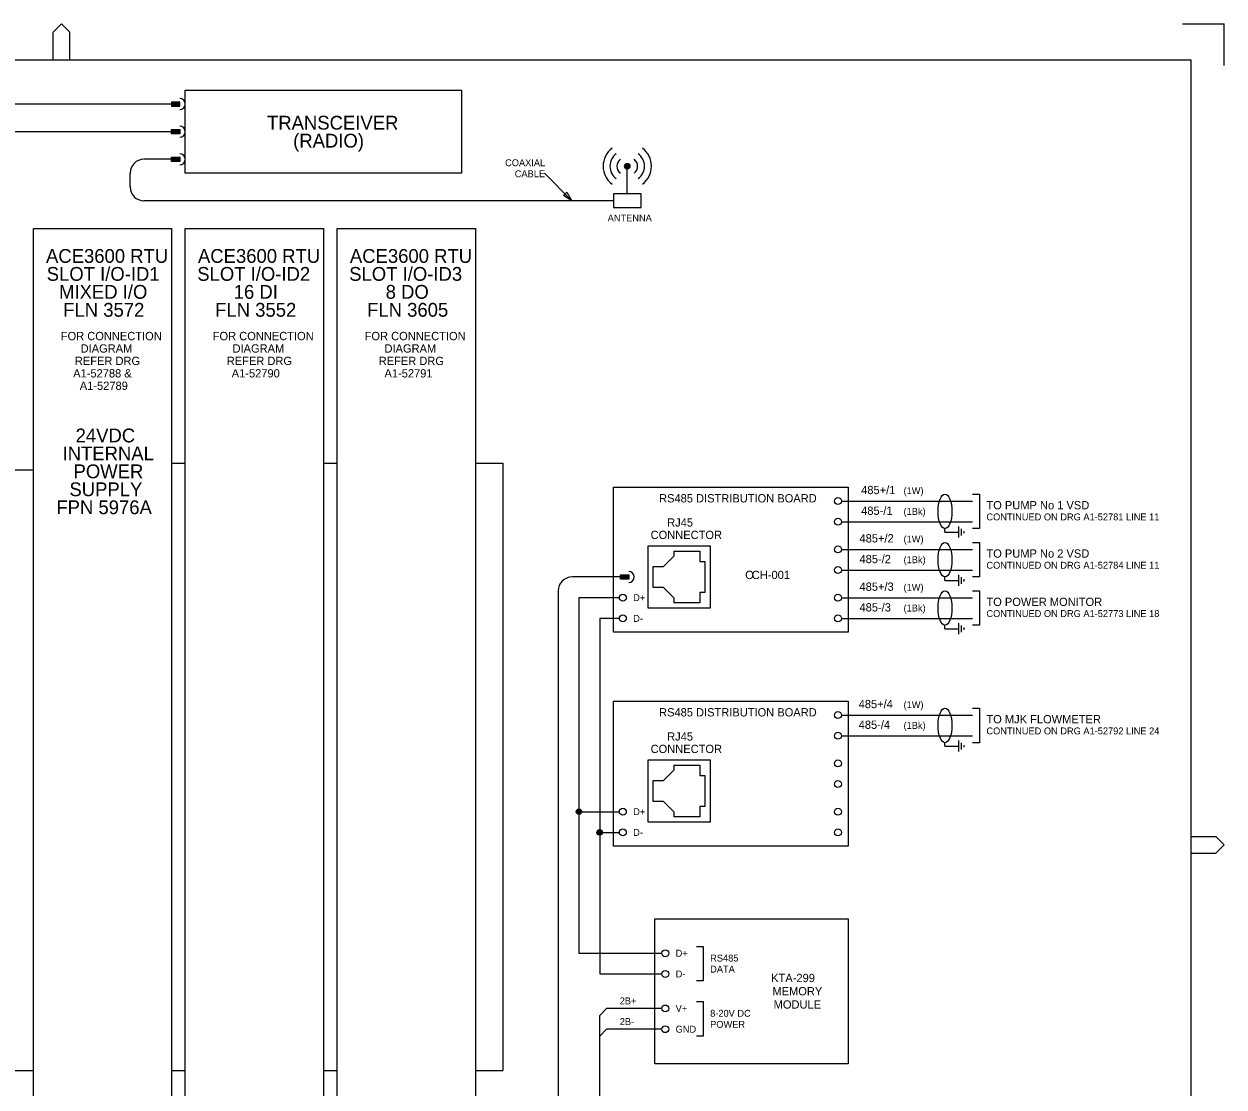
# Model space of a CAD drawing. Extents: x 0 to 841, y 0 to 594.
# Drawn here: x 406.6 to 841, y 209.1 to 594 of the extents above; entities that cross this region are included whole.
import ezdxf

# ---------------------------------------------------------------- set-up
doc = ezdxf.new("R2010")
doc.units = 0
for name, color, linetype in [('A1BORDER', 7, 'Continuous'), ('Level 1', 7, 'Continuous'), ('Level 10', 7, 'Continuous')]:
    doc.layers.add(name, color=color, linetype=linetype)

msp = doc.modelspace()

# ---------------------------------------------------------------- linework, layer by layer
at = {"layer": 'A1BORDER'}
for p, q in [((417.19, 591), (420.19, 594)), ((417.19, 581), (417.19, 591)), ((423.19, 591), (420.19, 594)), ((423.19, 581), (423.19, 591)), ((826, 594), (841, 594)), ((841, 579), (841, 594)), ((28, 581), (829, 581)), ((829, 581), (829, 15)), ((829, 299.76), (838, 299.76)), ((838, 299.76), (841, 296.76)), ((838, 293.76), (841, 296.76)), ((829, 293.76), (838, 293.76))]:
    msp.add_line(p, q, dxfattribs=at)
at = {"layer": 'Level 1'}
for p, q in [((460, 565), (395, 565)), ((463, 565.5), (460, 565.5)), ((463, 565.25), (460, 565.25)), ((463, 565), (460, 565)), ((463, 564.75), (460, 564.75)), ((463, 564.5), (460, 564.5)), ((460, 555), (235, 555)), ((460, 545), (450, 545)), ((445, 535), (445, 540)), ((604.97, 530), (594.97, 540)), ((624.97, 532.5), (624.97, 542.5)), ((620, 530), (450, 530)), ((460, 435), (465, 435)), ((515, 435), (520, 435)), ((570, 435), (580, 435)), ((580, 435), (580, 215)), ((370, 432.5), (410, 432.5)), ((702.5, 421.25), (750, 421.25)), ((702.5, 413.75), (750, 413.75)), ((740, 410), (740, 411.25)), ((740, 410), (745, 410)), ((638.12, 397.5), (641.88, 401.25)), ((641.88, 403.12), (651.25, 403.12)), ((641.88, 403.12), (641.88, 401.25)), ((651.25, 403.12), (651.25, 399.38)), ((702.5, 403.75), (750, 403.75)), ((634.38, 390), (634.38, 397.5)), ((634.38, 397.5), (638.12, 397.5)), ((651.25, 399.38), (653.12, 399.38)), ((653.12, 399.38), (653.12, 388.12)), ((702.5, 396.25), (750, 396.25)), ((622.5, 393.75), (605, 393.75)), ((740, 392.5), (740, 393.75)), ((740, 392.5), (745, 392.5)), ((600, 388.75), (600, 175)), ((638.12, 390), (634.38, 390)), ((641.88, 386.25), (638.12, 390)), ((653.12, 388.12), (651.25, 388.12)), ((651.25, 388.12), (651.25, 384.38)), ((622.13, 386.25), (607.5, 386.25)), ((607.5, 386.25), (607.5, 257.5)), ((641.88, 386.25), (641.88, 384.38)), ((651.25, 384.38), (641.88, 384.38)), ((702.5, 386.25), (750, 386.25)), ((622.13, 378.75), (615, 378.75)), ((615, 378.75), (615, 250)), ((702.5, 378.75), (750, 378.75)), ((740, 375), (740, 376.25)), ((740, 375), (745, 375)), ((702.5, 343.75), (750, 343.75)), ((702.5, 336.25), (750, 336.25)), ((740, 332.5), (740, 333.75)), ((740, 332.5), (745, 332.5)), ((638.12, 320), (641.88, 323.75)), ((641.88, 325.62), (651.25, 325.62)), ((641.88, 325.62), (641.88, 323.75)), ((651.25, 325.62), (651.25, 321.88)), ((651.25, 321.88), (653.12, 321.88)), ((653.12, 321.88), (653.12, 310.62)), ((634.38, 312.5), (634.38, 320)), ((634.38, 320), (638.12, 320)), ((607.5, 308.75), (622.13, 308.75)), ((638.12, 312.5), (634.38, 312.5)), ((641.88, 308.75), (638.12, 312.5)), ((641.88, 308.75), (641.88, 306.88)), ((653.12, 310.62), (651.25, 310.62)), ((651.25, 310.62), (651.25, 306.88)), ((651.25, 306.88), (641.88, 306.88)), ((615, 301.25), (622.13, 301.25)), ((607.5, 257.5), (637.5, 257.5)), ((615, 250), (637.5, 250)), ((617.5, 237.5), (615, 235)), ((615, 145), (615, 235)), ((637.5, 237.5), (617.5, 237.5)), ((617.5, 230), (615, 227.5)), ((637.5, 230), (617.5, 230)), ((370, 215), (410, 215)), ((460, 215), (465, 215)), ((515, 215), (520, 215)), ((570, 215), (580, 215))]:
    msp.add_line(p, q, dxfattribs=at)
for points in [[(465, 570), (565, 570), (565, 540), (465, 540)], [(603.11, 533.09), (604.97, 530), (601.88, 531.86)], [(619.97, 527.5), (629.97, 527.5), (629.97, 532.5), (619.97, 532.5)], [(410, 520), (460, 520), (460, 180), (410, 180)], [(465, 520), (515, 520), (515, 180), (465, 180)], [(520, 520), (570, 520), (570, 180), (520, 180)], [(620, 426.25), (705, 426.25), (705, 373.75), (620, 373.75)], [(655, 382.5), (632.5, 382.5), (632.5, 405), (655, 405)], [(620, 348.75), (705, 348.75), (705, 296.25), (620, 296.25)], [(655, 305), (632.5, 305), (632.5, 327.5), (655, 327.5)], [(635, 270), (705, 270), (705, 217.5), (635, 217.5)]]:
    msp.add_lwpolyline(points, close=True, dxfattribs=at)
for points in [[(750, 423.75), (752.5, 423.75), (752.5, 411.25), (750, 411.25)], [(750, 406.25), (752.5, 406.25), (752.5, 393.75), (750, 393.75)], [(750, 388.75), (752.5, 388.75), (752.5, 376.25), (750, 376.25)], [(750, 346.25), (752.5, 346.25), (752.5, 333.75), (750, 333.75)], [(650, 260), (652.5, 260), (652.5, 247.5), (650, 247.5)], [(650, 240), (652.5, 240), (652.5, 227.5), (650, 227.5)]]:
    msp.add_lwpolyline(points, dxfattribs=at)
for centre, radius, start, end in [((624.35, 542.5), 8.12, 126.8699, 233.1301), ((625.6, 542.5), 8.12, 306.8699, 53.1301), ((450, 540), 5, 90, 180), ((624.35, 542.5), 5.62, 126.8699, 233.1301), ((624.35, 542.5), 3.12, 126.8699, 233.1301), ((625.6, 542.5), 3.12, 306.8699, 53.1301), ((625.6, 542.5), 5.62, 306.8699, 53.1301), ((450, 535), 5, 180, 270), ((605, 388.75), 5, 90, 180)]:
    msp.add_arc(centre, radius, start, end, dxfattribs=at)
for centre in [(740, 417.5), (740, 400), (740, 382.5), (740, 340)]:
    msp.add_ellipse(centre, major_axis=(0, 6.25), ratio=0.4, dxfattribs=at)
at = {"layer": 'Level 10'}
for p, q in [((463, 555.48), (460, 555.48)), ((463, 555.18), (460, 555.18)), ((463, 554.88), (460, 554.88)), ((463, 554.58), (460, 554.58)), ((463, 554.28), (460, 554.28)), ((463, 545.48), (460, 545.48)), ((463, 545.18), (460, 545.18)), ((463, 544.88), (460, 544.88)), ((463, 544.58), (460, 544.58)), ((463, 544.28), (460, 544.28)), ((624.26, 543.2), (625.68, 543.2)), ((624.97, 543.5), (624.97, 543.5)), ((623.98, 542.6), (625.96, 542.6)), ((623.99, 542.3), (625.95, 542.3)), ((624.05, 542.9), (625.89, 542.9)), ((624.1, 542), (625.84, 542)), ((624.37, 541.7), (625.57, 541.7)), ((745, 408), (745, 412)), ((746, 408.8), (746, 411.2)), ((747, 409.6), (747, 410.4)), ((625.5, 394.23), (622.5, 394.23)), ((625.5, 393.93), (622.5, 393.93)), ((625.5, 393.63), (622.5, 393.63)), ((625.5, 393.33), (622.5, 393.33)), ((625.5, 393.03), (622.5, 393.03)), ((745, 390.5), (745, 394.5)), ((746, 391.3), (746, 393.7)), ((747, 392.1), (747, 392.9)), ((745, 373), (745, 377)), ((746, 373.8), (746, 376.2)), ((747, 374.6), (747, 375.4)), ((745, 330.5), (745, 334.5)), ((746, 331.3), (746, 333.7)), ((747, 332.1), (747, 332.9)), ((606.5, 308.75), (606.5, 308.75)), ((606.8, 308.04), (606.8, 309.46)), ((607.1, 307.83), (607.1, 309.67)), ((607.4, 307.76), (607.4, 309.74)), ((607.7, 307.77), (607.7, 309.73)), ((608, 307.88), (608, 309.62)), ((608.3, 308.15), (608.3, 309.35)), ((614, 301.25), (614, 301.25)), ((614.3, 300.54), (614.3, 301.96)), ((614.6, 300.33), (614.6, 302.17)), ((614.9, 300.26), (614.9, 302.24)), ((615.2, 300.27), (615.2, 302.23)), ((615.5, 300.38), (615.5, 302.12)), ((615.8, 300.65), (615.8, 301.85))]:
    msp.add_line(p, q, dxfattribs=at)
for points in [[(463, 565.75), (460, 565.75), (460, 564.25), (463, 564.25)], [(463, 554.25), (460, 554.25), (460, 555.75), (463, 555.75)], [(463, 544.25), (460, 544.25), (460, 545.75), (463, 545.75)], [(625.5, 393), (622.5, 393), (622.5, 394.5), (625.5, 394.5)]]:
    msp.add_lwpolyline(points, close=True, dxfattribs=at)
for centre, radius in [((624.97, 542.5), 1), ((701.25, 421.25), 1.25), ((701.25, 413.75), 1.25), ((701.25, 403.75), 1.25), ((701.25, 396.25), 1.25), ((623.38, 386.25), 1.25), ((701.25, 386.25), 1.25), ((623.38, 378.75), 1.25), ((701.25, 378.75), 1.25), ((701.25, 343.75), 1.25), ((701.25, 336.25), 1.25), ((701.25, 326.25), 1.25), ((701.25, 318.75), 1.25), ((607.5, 308.75), 1), ((623.38, 308.75), 1.25), ((701.25, 308.75), 1.25), ((615, 301.25), 1), ((623.38, 301.25), 1.25), ((701.25, 301.25), 1.25), ((638.75, 257.5), 1.25), ((638.75, 250), 1.25), ((638.75, 237.5), 1.25), ((638.75, 230), 1.25)]:
    msp.add_circle(centre, radius, dxfattribs=at)
for centre in [(463, 565), (463, 555), (463, 545), (625.5, 393.75)]:
    msp.add_arc(centre, 2, 270, 90, dxfattribs=at)

# ---------------------------------------------------------------- texts
at = {"layer": 'Level 1'}
for s, height, p in [('TRANSCEIVER', 5, (494.58, 555.75)), ('(RADIO)', 5, (504.04, 549.25)), ('COAXIAL', 2.5, (580.77, 542.5)), ('CABLE', 2.5, (584.26, 538.5)), ('ANTENNA', 2.5, (617.9, 522.5)), ('ACE3600 RTU', 5, (414.58, 507.5)), ('ACE3600 RTU', 5, (469.58, 507.5)), ('ACE3600 RTU', 5, (524.58, 507.5)), ('SLOT I/O-ID1', 5, (414.83, 501)), ('SLOT I/O-ID2', 5, (469.33, 501)), ('SLOT I/O-ID3', 5, (524.33, 501)), ('MIXED I/O', 5, (419.31, 494.5)), ('16 DI', 5, (482.53, 494.5)), ('8 DO', 5, (537.53, 494.5)), ('FLN 3572', 5, (420.81, 488)), ('FLN 3552', 5, (475.81, 488)), ('FLN 3605', 5, (530.81, 488)), ('FOR CONNECTION', 3, (419.93, 479.5)), ('FOR CONNECTION', 3, (474.93, 479.5)), ('FOR CONNECTION', 3, (529.93, 479.5)), ('DIAGRAM', 3, (427.1, 475)), ('DIAGRAM', 3, (482.1, 475)), ('DIAGRAM', 3, (537.1, 475)), ('REFER DRG', 3, (425.01, 470.5)), ('REFER DRG', 3, (480.01, 470.5)), ('REFER DRG', 3, (535.01, 470.5)), ('A1-52788 &', 3, (424.41, 466)), ('A1-52790', 3, (481.8, 466)), ('A1-52791', 3, (537.1, 466)), ('A1-52789', 3, (426.8, 461.5)), ('24VDC', 5, (425.29, 442.5)), ('INTERNAL', 5, (420.56, 436)), ('POWER', 5, (424.54, 429.5)), ('SUPPLY', 5, (423.05, 423)), ('485+/1', 3, (709.65, 423.75)), ('(1W)', 2.5, (725, 423.75)), ('FPN 5976A', 5, (418.32, 416.5)), ('RS485 DISTRIBUTION BOARD', 3, (636.5, 420.75)), ('485-/1', 3, (709.65, 416.25)), ('(1Bk)', 2.5, (725, 416.25)), ('TO PUMP No 1 VSD', 3, (755, 418.25)), ('RJ45', 3, (639.42, 412)), ('CONTINUED ON DRG A1-52781 LINE 11', 2.5, (755, 414.25)), ('CONNECTOR', 3, (633.44, 407.5)), ('485+/2', 3, (709.05, 406.25)), ('(1W)', 2.5, (725, 406.25)), ('485-/2', 3, (709.05, 398.75)), ('(1Bk)', 2.5, (725, 398.75)), ('TO PUMP No 2 VSD', 3, (755, 400.75)), ('O', 3, (667.68, 393)), ('CH-001', 3, (670.07, 393)), ('CONTINUED ON DRG A1-52784 LINE 11', 2.5, (755, 396.75)), ('485+/3', 3, (709.05, 388.75)), ('(1W)', 2.5, (725, 388.75)), ('D+', 2.5, (627.13, 385)), ('485-/3', 3, (709.05, 381.25)), ('(1Bk)', 2.5, (725, 381.25)), ('TO POWER MONITOR', 3, (755, 383.25)), ('D-', 2.5, (627.13, 377.5)), ('CONTINUED ON DRG A1-52773 LINE 18', 2.5, (755, 379.25)), ('485+/4', 3, (708.75, 346.25)), ('(1W)', 2.5, (725, 346.25)), ('RS485 DISTRIBUTION BOARD', 3, (636.5, 343.25)), ('TO MJK FLOWMETER', 3, (755, 340.75)), ('485-/4', 3, (708.75, 338.75)), ('(1Bk)', 2.5, (725, 338.75)), ('CONTINUED ON DRG A1-52792 LINE 24', 2.5, (755, 336.75)), ('RJ45', 3, (639.42, 334.5)), ('CONNECTOR', 3, (633.44, 330)), ('D+', 2.5, (627.13, 307.5)), ('D-', 2.5, (627.13, 300)), ('D+', 2.5, (642.5, 256.25)), ('RS485', 2.5, (655, 254.5)), ('DATA', 2.5, (655, 250.5)), ('D-', 2.5, (642.5, 248.75)), ('KTA-299', 3, (677.08, 247.05)), ('MEMORY', 3, (677.53, 242.25)), ('2B+', 2.5, (622.26, 239)), ('MODULE', 3, (677.98, 237.45)), ('V+', 2.5, (642.5, 236.25)), ('8-20V DC', 2.5, (655, 234.5)), ('2B-', 2.5, (622.26, 231.5)), ('GND', 2.5, (642.5, 228.75)), ('POWER', 2.5, (655, 230.5))]:
    msp.add_text(s, height=height, dxfattribs=at).set_placement(p)

doc.saveas('drawing.dxf')
